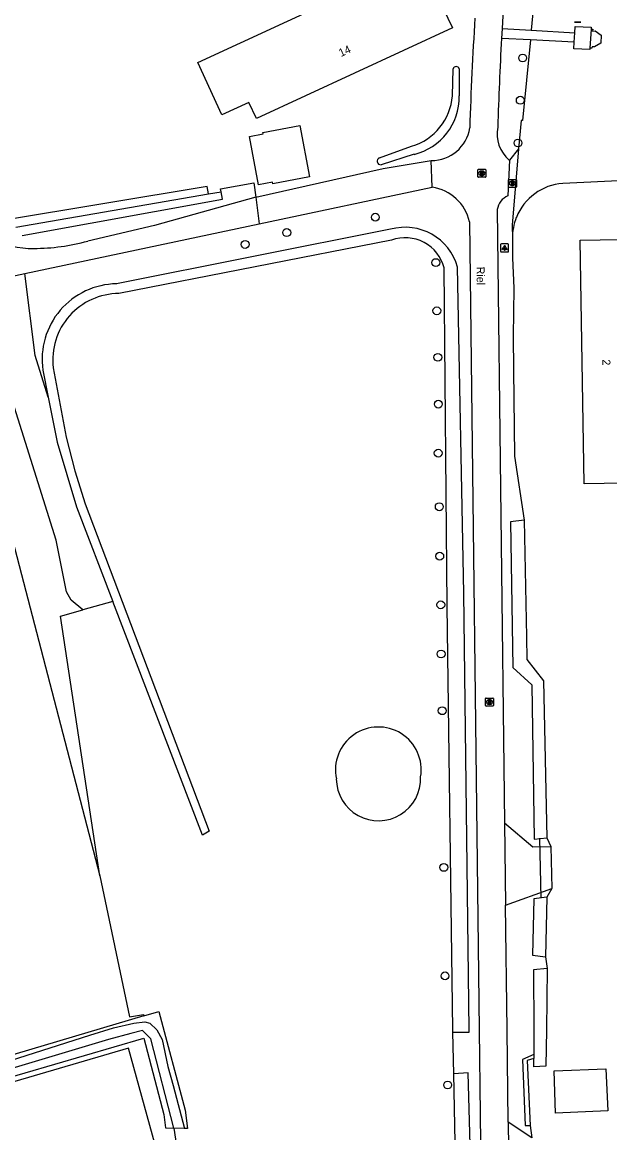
# Model space of a CAD drawing. Extents: x 163863 to 164644, y 379566 to 382155.
# Drawn here: x 164384.5 to 164457.9, y 381487.2 to 381625.9 of the extents above; entities that cross this region are included whole.
import ezdxf

# ---------------------------------------------------------------- set-up
doc = ezdxf.new("R2010")
doc.units = 0
for name, color, linetype in [('IMGEO_Boom', 7, 'Continuous'), ('IMGEO_Brandkraan', 7, 'Continuous'), ('IMGEO_Duiker', 7, 'Continuous'), ('IMGEO_Erf', 7, 'Continuous'), ('IMGEO_Grasland_overig', 7, 'Continuous'), ('IMGEO_Greppel_droge_sloot', 7, 'Continuous'), ('IMGEO_Groenvoorziening', 7, 'Continuous'), ('IMGEO_Haag', 7, 'Continuous'), ('IMGEO_Informatiebord', 7, 'Continuous'), ('IMGEO_Lichtpunt', 7, 'Continuous'), ('IMGEO_Loofbos', 7, 'Continuous'), ('IMGEO_Openbare_ruimte_label', 7, 'Continuous'), ('IMGEO_Pand', 7, 'Continuous'), ('IMGEO_Pand_nummerreeks', 7, 'Continuous'), ('IMGEO_Rijbaan_lokaal_gesloten', 7, 'Continuous'), ('IMGEO_Rijbaan_lokaal_halfverhard', 7, 'Continuous'), ('IMGEO_Rijbaan_lokaal_onverhard', 7, 'Continuous'), ('IMGEO_Rioolput', 7, 'Continuous'), ('IMGEO_Voetpad_open', 7, 'Continuous'), ('IMGEO_Waterloop', 7, 'Continuous')]:
    doc.layers.add(name, color=color, linetype=linetype)

msp = doc.modelspace()

# ---------------------------------------------------------------- linework, layer by layer
at = {"layer": 'IMGEO_Boom'}
for centre in [(164447.05, 381621.41), (164446.75, 381616.13), (164446.46, 381610.79), (164428.64, 381601.52), (164417.58, 381599.6), (164412.38, 381598.12), (164436.2, 381595.85), (164436.33, 381589.83), (164436.46, 381584.02), (164436.51, 381578.17), (164436.5, 381572.05), (164436.63, 381565.35), (164436.69, 381559.18), (164436.82, 381553.1), (164436.86, 381546.96), (164437, 381539.87), (164437.2, 381520.3), (164437.35, 381506.75), (164437.68, 381493.12)]:
    msp.add_circle(centre, 0.489, dxfattribs=at)
at = {"layer": 'IMGEO_Brandkraan'}
for p, q in [((164445.26, 381605.33), (164445.26, 381606.18)), ((164445.34, 381606.25), (164446.19, 381606.25)), ((164446.26, 381606.18), (164446.26, 381605.33)), ((164446.19, 381605.25), (164445.34, 381605.25)), ((164445.75, 381606.03), (164445.77, 381606.03)), ((164445.77, 381605.47), (164445.75, 381605.47))]:
    msp.add_line(p, q, dxfattribs=at)
for points in [[(164445.26, 381605.33), (164445.26, 381606.18)], [(164445.34, 381606.25), (164446.19, 381606.25)], [(164446.26, 381606.18), (164446.26, 381605.33)], [(164446.19, 381605.25), (164445.34, 381605.25)], [(164445.61, 381605.95), (164445.61, 381605.55), (164445.82, 381605.55)], [(164445.84, 381605.95), (164445.61, 381605.95)], [(164445.79, 381605.87), (164445.73, 381605.87), (164445.73, 381605.8)], [(164445.73, 381605.8), (164445.79, 381605.8)], [(164445.8, 381605.72), (164445.73, 381605.72), (164445.73, 381605.64)], [(164445.73, 381605.64), (164445.8, 381605.64)]]:
    msp.add_lwpolyline(points, dxfattribs=at)
for centre, radius, start, end in [((164445.34, 381606.18), 0.0765, 91.552, 178.448), ((164445.34, 381606.18), 0.0765, 91.552, 178.448), ((164446.19, 381606.18), 0.0765, 1.552, 88.448), ((164446.19, 381606.18), 0.0765, 1.552, 88.448), ((164445.34, 381605.33), 0.0765, 181.552, 268.448), ((164445.34, 381605.33), 0.0765, 181.552, 268.448), ((164445.79, 381605.83), 0.0379, 267.8285, 90.9355), ((164445.8, 381605.68), 0.0404, 269.8759, 90.5077), ((164445.83, 381605.8), 0.251, 268.6676, 293.5347), ((164445.84, 381605.81), 0.145, 59.4692, 91.5367), ((164445.87, 381605.86), 0.0922, 285.5137, 58.1501), ((164445.87, 381605.66), 0.105, 301.3115, 78.989), ((164446.19, 381605.33), 0.0765, 271.552, 358.448), ((164446.19, 381605.33), 0.0765, 271.552, 358.448)]:
    msp.add_arc(centre, radius, start, end, dxfattribs=at)
for centre, major_axis, ratio, start_param, end_param in [((164445.75, 381605.75), (-0.387, 0.002), 0.722429, 4.712389, 7.853982), ((164445.77, 381605.75), (-0.39, 0.002), 0.717154, 1.570796, 4.712389)]:
    msp.add_ellipse(centre, major_axis=major_axis, ratio=ratio, start_param=start_param, end_param=end_param, dxfattribs=at)
at = {"layer": 'IMGEO_Duiker'}
msp.add_lwpolyline([(164449.15, 381523.97), (164449.33, 381516.45)], dxfattribs=at)
at = {"layer": 'IMGEO_Erf'}
msp.add_lwpolyline([(164399.71, 381501.75), (164380.24, 381495.98)], dxfattribs=at)
at = {"layer": 'IMGEO_Grasland_overig'}
for points in [[(164392.11, 381552.47), (164390.65, 381553.68), (164390.08, 381554.71), (164388.77, 381561.19), (164381.76, 381583.47), (164380.51, 381593.56)], [(164375.48, 381589.55), (164377.05, 381585.25), (164394.23, 381519.23)], [(164348.35, 381518.62), (164349.7, 381517.97), (164353.09, 381515.54), (164355.98, 381512.51), (164367, 381500.41), (164372.5, 381495.24), (164374.19, 381493.46), (164376.45, 381492.51), (164378.9, 381492.55), (164381.15, 381493.56), (164399.72, 381498.97), (164402.22, 381489.44), (164402.44, 381487.77), (164403.46, 381487.71)], [(164404.26, 381474.32), (164397.81, 381497.74), (164374.92, 381491), (164348.35, 381518.62)], [(164448.45, 381496.92), (164447.04, 381496.29), (164447.36, 381488.05), (164447.99, 381488.08)], [(164448.45, 381496.45), (164447.62, 381496.18), (164447.99, 381488.08)]]:
    msp.add_lwpolyline(points, dxfattribs=at)
at = {"layer": 'IMGEO_Greppel_droge_sloot'}
for points in [[(164438.27, 381616.7), (164438.38, 381620.04)], [(164439.11, 381620.04), (164439.12, 381616.67)], [(164429.16, 381608.94), (164433.18, 381610.4)], [(164433.49, 381609.38), (164429.36, 381608.07)]]:
    msp.add_lwpolyline(points, dxfattribs=at)
for centre, radius, start, end in [((164438.74, 381619.97), 0.374, 10.7468, 169.8768), ((164431.19, 381617.21), 7.1, 286.3074, 355.8959), ((164431.74, 381616.55), 7.39, 283.7517, 0.901), ((164429.33, 381608.52), 0.455, 112.0307, 273.6908)]:
    msp.add_arc(centre, radius, start, end, dxfattribs=at)
at = {"layer": 'IMGEO_Groenvoorziening'}
for points in [[(164452.88, 381674.52), (164448.12, 381624.87)], [(164446.54, 381610.04), (164445.73, 381600.53), (164445.79, 381598.85)], [(164473.79, 381606.76), (164452.07, 381605.75)], [(164409.37, 381604.7), (164409.29, 381605.07), (164413.47, 381605.82), (164413.71, 381604.01)], [(164445.79, 381598.85), (164445.76, 381596.44), (164445.96, 381592.66), (164445.85, 381586.66), (164445.92, 381582.44), (164446.04, 381571.66), (164447.24, 381563.68)], [(164387.77, 381579.05), (164386.14, 381584.23), (164384.86, 381594.48)], [(164450.08, 381523.98), (164450.55, 381522.92)], [(164450.68, 381517.67), (164450.07, 381516.57)], [(164449.91, 381509.12), (164450.1, 381507.69)], [(164447.99, 381488.08), (164448.2, 381486.51)]]:
    msp.add_lwpolyline(points, dxfattribs=at)
for centre, radius, start, end in [((164452.55, 381599), 6.76, 94.0969, 158.32), ((164452.52, 381599), 6.74, 158.2733, 181.2961)]:
    msp.add_arc(centre, radius, start, end, dxfattribs=at)
at = {"layer": 'IMGEO_Haag'}
msp.add_lwpolyline([(164407.8, 381604.43), (164407.63, 381605.35), (164382.05, 381601.1), (164338.92, 381665.18), (164338.35, 381664.78)], dxfattribs=at)
at = {"layer": 'IMGEO_Informatiebord'}
for p, q in [((164454.33, 381625.88), (164453.54, 381625.88)), ((164453.54, 381625.88), (164454.33, 381625.88))]:
    msp.add_line(p, q, dxfattribs=at)
at = {"layer": 'IMGEO_Lichtpunt'}
for p, q in [((164444.3, 381598.09), (164444.3, 381597.28)), ((164444.3, 381598.09), (164444.3, 381597.28)), ((164445.2, 381598.18), (164444.39, 381598.18)), ((164445.2, 381598.18), (164444.39, 381598.18)), ((164445.29, 381597.28), (164445.29, 381598.09)), ((164445.29, 381597.28), (164445.29, 381598.09)), ((164444.39, 381597.18), (164445.2, 381597.18)), ((164444.39, 381597.18), (164445.2, 381597.18))]:
    msp.add_line(p, q, dxfattribs=at)
for points in [[(164444.67, 381597.75), (164444.71, 381597.72), (164444.52, 381597.46), (164444.48, 381597.49), (164444.67, 381597.75)], [(164444.88, 381597.72), (164444.92, 381597.75), (164445.11, 381597.49), (164445.07, 381597.46), (164444.88, 381597.72)], [(164444.77, 381597.7), (164444.82, 381597.7), (164444.82, 381597.38), (164444.77, 381597.38), (164444.77, 381597.7)]]:
    msp.add_lwpolyline(points, dxfattribs=at)
msp.add_circle((164444.8, 381597.88), 0.0994, dxfattribs=at)
for centre, start, end in [((164444.39, 381598.09), 90, 180), ((164444.39, 381598.09), 90, 180), ((164445.2, 381598.09), 0, 90), ((164445.2, 381598.09), 0, 90), ((164444.39, 381597.28), 180, 270), ((164444.39, 381597.28), 180, 270), ((164445.2, 381597.28), 270, 0), ((164445.2, 381597.28), 270, 360)]:
    msp.add_arc(centre, 0.0946, start, end, dxfattribs=at)
at = {"layer": 'IMGEO_Loofbos'}
for points in [[(164448.01, 381623.67), (164447.04, 381613.6), (164446.85, 381613.61), (164446.54, 381610.04)], [(164446.54, 381610.04), (164445.39, 381608.65)], [(164395.86, 381553.52), (164392.11, 381552.47)], [(164394.23, 381519.23), (164389.32, 381551.69), (164392.11, 381552.47)], [(164394.23, 381519.23), (164397.93, 381501.62), (164399.68, 381501.92), (164399.71, 381501.75)], [(164399.71, 381501.75), (164401.6, 381502.3), (164404.9, 381489.96), (164405.2, 381487.7), (164404.81, 381487.67)], [(164438.46, 381494.53), (164438.34, 381499.7)], [(164403.46, 381487.71), (164404.03, 381484.15)]]:
    msp.add_lwpolyline(points, dxfattribs=at)
for centre, radius, start, end in [((164429.02, 381532.48), 5.36, 350.5628, 192.1236), ((164429.04, 381531.4), 5.27, 180.5064, 2.18)]:
    msp.add_arc(centre, radius, start, end, dxfattribs=at)
at = {"layer": 'IMGEO_Pand'}
for points in [[(164434.22, 381633.69), (164438.27, 381625.17), (164413.78, 381613.84), (164412.85, 381615.86), (164409.48, 381614.3), (164406.45, 381620.84), (164434.22, 381633.69)], [(164455.59, 381625), (164455.46, 381622.64)], [(164455.59, 381625), (164455.8, 381624.99), (164455.79, 381624.77), (164456.11, 381624.78), (164456.86, 381624.28), (164456.82, 381623.27), (164456.04, 381622.8), (164455.72, 381622.82), (164455.71, 381622.62), (164455.46, 381622.64)], [(164412.91, 381611.62), (164414.64, 381611.95), (164414.61, 381612.12), (164419.21, 381612.99), (164420.42, 381606.58), (164415.82, 381605.7), (164415.78, 381605.88), (164414.06, 381605.55), (164412.91, 381611.62)], [(164464.35, 381568.37), (164459.74, 381568.3), (164454.74, 381568.22), (164454.24, 381598.65), (164459.24, 381598.75), (164463.87, 381598.84), (164464.35, 381568.37)], [(164457.68, 381489.91), (164451.15, 381489.61), (164450.97, 381494.89), (164457.45, 381495.15), (164457.68, 381489.91)]]:
    msp.add_lwpolyline(points, dxfattribs=at)
at = {"layer": 'IMGEO_Rijbaan_lokaal_gesloten'}
for points in [[(164444.47, 381625.08), (164444.44, 381624.46), (164444.4, 381623.85)], [(164435.74, 381605.27), (164435.64, 381608.59)], [(164445.39, 381608.65), (164445.21, 381604.21)], [(164443.88, 381602.47), (164444.8, 381525.85)], [(164440.42, 381600.95), (164441.6, 381500), (164441.98, 381468.27), (164442.05, 381465.53), (164442.22, 381458.62), (164442.22, 381457.68)], [(164444.8, 381525.85), (164444.92, 381515.57)], [(164445.25, 381488.48), (164445.11, 381500), (164444.92, 381515.57)], [(164445.25, 381488.48), (164445.36, 381478.81)]]:
    msp.add_lwpolyline(points, dxfattribs=at)
for centre, radius, start, end in [((164886.52, 381599.85), 442.77, 170.1772, 176.7344), ((164930.76, 381596.32), 490.6, 176.4854, 178.0894), ((164883.32, 381600.01), 439.56, 176.8905, 178.3368), ((164435.65, 381613.44), 4.85, 269.9071, 350.8532), ((164448.06, 381611.91), 4.21, 168.2264, 230.5312), ((164434.91, 381599.68), 5.65, 12.9621, 81.5794), ((164446.13, 381602.13), 2.27, 113.8211, 171.5393)]:
    msp.add_arc(centre, radius, start, end, dxfattribs=at)
at = {"layer": 'IMGEO_Rijbaan_lokaal_halfverhard'}
for points in [[(164413.71, 381604.01), (164429.61, 381607.59), (164435.64, 381608.59)], [(164414.14, 381600.68), (164435.74, 381605.27)], [(164413.71, 381604.01), (164414.14, 381600.68)]]:
    msp.add_lwpolyline(points, dxfattribs=at)
at = {"layer": 'IMGEO_Rijbaan_lokaal_onverhard'}
for points in [[(164413.71, 381604.01), (164401.06, 381600.47), (164392.72, 381598.54)], [(164384.86, 381594.48), (164414.14, 381600.68)], [(164380.51, 381593.56), (164384.86, 381594.48)]]:
    msp.add_lwpolyline(points, dxfattribs=at)
for centre, radius, start, end in [((164385.9, 381609.07), 11.46, 242.7973, 270.3915), ((164385.95, 381623.04), 25.42, 270.0677, 285.4619)]:
    msp.add_arc(centre, radius, start, end, dxfattribs=at)
at = {"layer": 'IMGEO_Rioolput'}
for p, q in [((164441.45, 381606.58), (164441.45, 381607.43)), ((164441.52, 381607.51), (164442.38, 381607.51)), ((164442.45, 381607.43), (164442.45, 381606.58)), ((164442.38, 381606.51), (164441.52, 381606.51)), ((164441.94, 381607.29), (164441.96, 381607.29)), ((164441.96, 381606.73), (164441.94, 381606.73)), ((164442.41, 381540.52), (164442.41, 381541.38)), ((164442.48, 381541.45), (164443.33, 381541.45)), ((164442.89, 381541.23), (164442.92, 381541.23)), ((164443.41, 381541.38), (164443.41, 381540.52)), ((164443.33, 381540.45), (164442.48, 381540.45)), ((164442.92, 381540.67), (164442.89, 381540.67))]:
    msp.add_line(p, q, dxfattribs=at)
for points in [[(164441.45, 381606.58), (164441.45, 381607.43)], [(164441.52, 381607.51), (164442.38, 381607.51)], [(164442.45, 381607.43), (164442.45, 381606.58)], [(164442.38, 381606.51), (164441.52, 381606.51)], [(164442.04, 381607.2), (164441.79, 381607.21), (164441.79, 381606.81)], [(164441.79, 381606.81), (164441.91, 381606.81), (164441.91, 381606.97), (164441.92, 381606.97)], [(164441.97, 381607.13), (164441.91, 381607.13), (164441.91, 381607.04)], [(164441.91, 381607.04), (164441.96, 381607.04)], [(164441.97, 381606.94), (164442.04, 381606.81), (164442.18, 381606.81), (164442.11, 381606.93)], [(164442.41, 381540.52), (164442.41, 381541.38)], [(164442.48, 381541.45), (164443.33, 381541.45)], [(164442.99, 381541.15), (164442.74, 381541.15), (164442.74, 381540.75)], [(164442.74, 381540.75), (164442.87, 381540.75), (164442.87, 381540.91), (164442.88, 381540.91)], [(164442.92, 381541.07), (164442.87, 381541.07), (164442.87, 381540.99)], [(164442.87, 381540.99), (164442.92, 381540.99)], [(164442.92, 381540.88), (164443, 381540.75), (164443.13, 381540.75), (164443.07, 381540.88)], [(164443.41, 381541.38), (164443.41, 381540.52)], [(164443.33, 381540.45), (164442.48, 381540.45)]]:
    msp.add_lwpolyline(points, dxfattribs=at)
for centre, radius, start, end in [((164441.53, 381607.43), 0.0765, 91.552, 178.448), ((164441.53, 381607.43), 0.0765, 91.552, 178.448), ((164442.37, 381607.43), 0.0765, 1.552, 88.448), ((164442.37, 381607.43), 0.0765, 1.552, 88.448), ((164441.53, 381606.58), 0.0765, 181.552, 268.448), ((164441.53, 381606.58), 0.0765, 181.552, 268.448), ((164441.92, 381606.92), 0.0533, 26.0293, 88.6989), ((164441.95, 381607.23), 0.19, 274.7715, 282.9687), ((164441.97, 381607.03), 0.0964, 77.0061, 93.1865), ((164441.99, 381607.09), 0.0378, 276.6634, 79.6772), ((164442.04, 381607.09), 0.109, 350.3612, 89.416), ((164442.04, 381607.09), 0.112, 277.5842, 350.9817), ((164442.02, 381606.88), 0.108, 29.5134, 73.7905), ((164442.37, 381606.58), 0.0765, 271.552, 358.448), ((164442.37, 381606.58), 0.0765, 271.552, 358.448), ((164442.48, 381541.37), 0.0765, 91.552, 178.448), ((164442.48, 381541.37), 0.0765, 91.552, 178.448), ((164442.88, 381540.86), 0.0533, 26.0293, 88.6989), ((164442.93, 381540.97), 0.0964, 77.0061, 93.1865), ((164442.9, 381541.18), 0.19, 274.7715, 282.9687), ((164442.94, 381541.03), 0.0378, 276.6634, 79.6772), ((164442.99, 381541.04), 0.109, 350.3612, 89.416), ((164442.99, 381541.04), 0.112, 277.5842, 350.9817), ((164442.98, 381540.82), 0.108, 29.5134, 73.7905), ((164443.33, 381541.37), 0.0765, 1.552, 88.448), ((164443.33, 381541.37), 0.0765, 1.552, 88.448), ((164442.48, 381540.52), 0.0765, 181.552, 268.448), ((164442.48, 381540.52), 0.0765, 181.552, 268.448), ((164443.33, 381540.52), 0.0765, 271.552, 358.448), ((164443.33, 381540.52), 0.0765, 271.552, 358.448)]:
    msp.add_arc(centre, radius, start, end, dxfattribs=at)
for centre, major_axis, ratio, start_param, end_param in [((164441.94, 381607.01), (-0.387, 0.002), 0.722429, 4.712389, 7.853982), ((164441.96, 381607.01), (-0.39, 0.002), 0.717154, 1.570796, 4.712389), ((164442.89, 381540.95), (-0.387, 0.002), 0.722429, 4.712389, 7.853982), ((164442.92, 381540.95), (-0.39, 0.002), 0.717154, 1.570796, 4.712389)]:
    msp.add_ellipse(centre, major_axis=major_axis, ratio=ratio, start_param=start_param, end_param=end_param, dxfattribs=at)
at = {"layer": 'IMGEO_Voetpad_open'}
for points in [[(164444.47, 381625.08), (164448.12, 381624.87)], [(164448.12, 381624.87), (164453.56, 381624.57)], [(164453.5, 381623.38), (164453.56, 381624.57)], [(164453.56, 381624.57), (164453.61, 381625.36), (164455.59, 381625.27), (164455.59, 381625)], [(164448.01, 381623.67), (164444.4, 381623.85)], [(164453.5, 381623.38), (164448.01, 381623.67)], [(164455.46, 381622.64), (164455.45, 381622.46), (164453.45, 381622.56), (164453.5, 381623.38)], [(164444.8, 381525.85), (164448.32, 381522.87), (164450.55, 381522.92)], [(164450.55, 381522.92), (164450.68, 381517.67)], [(164444.92, 381515.57), (164450.68, 381517.67)], [(164448.2, 381486.51), (164445.25, 381488.48)]]:
    msp.add_lwpolyline(points, dxfattribs=at)
at = {"layer": 'IMGEO_Waterloop'}
for points in [[(164384.53, 381599.22), (164409.57, 381603.76), (164409.37, 381604.7)], [(164407.8, 381604.43), (164409.37, 381604.7)], [(164383.73, 381600.26), (164407.8, 381604.43)], [(164430.54, 381600.01), (164396.33, 381593.2)], [(164430.68, 381598.65), (164396.62, 381591.99)], [(164438.34, 381499.7), (164438.34, 381500), (164437.6, 381552.99), (164437.24, 381595.18)], [(164438.34, 381499.7), (164440.38, 381499.71), (164440.38, 381500), (164439.69, 381554.54), (164438.92, 381595.29)], [(164388.41, 381582.72), (164390.02, 381574.06), (164391.09, 381569.85), (164392.41, 381565.7), (164407.87, 381524.82), (164407.05, 381524.34), (164395.86, 381553.52)], [(164387.11, 381582.42), (164387.77, 381579.05)], [(164387.77, 381579.05), (164388.89, 381573.41), (164391.32, 381565.35), (164395.86, 381553.52)], [(164447.24, 381563.68), (164445.54, 381563.46), (164445.82, 381545.26), (164448.18, 381543.12), (164448.5, 381523.83), (164450.08, 381523.98)], [(164447.24, 381563.68), (164447.52, 381549.09), (164447.58, 381546.29), (164449.66, 381543.61), (164450.08, 381523.98)], [(164450.07, 381516.57), (164448.43, 381516.36), (164448.27, 381509.34), (164449.91, 381509.12)], [(164450.07, 381516.57), (164449.91, 381509.12)], [(164450.1, 381507.69), (164448.42, 381507.52), (164448.44, 381500), (164448.45, 381496.92)], [(164450.1, 381507.69), (164450.01, 381500), (164449.96, 381495.46), (164448.45, 381495.4), (164448.45, 381496.45)], [(164381.07, 381495.55), (164392.99, 381499.33), (164395.92, 381500.28), (164398.49, 381500.86), (164399.86, 381500.99), (164400.48, 381500.83), (164401.35, 381500), (164402, 381498.79), (164402.74, 381495.45), (164403.41, 381493.05), (164404.81, 381487.67)], [(164403.46, 381487.71), (164400.58, 381498.87), (164399.54, 381499.92), (164398.09, 381499.57), (164395.31, 381498.82), (164382.41, 381494.93)], [(164448.45, 381496.92), (164448.45, 381496.45)], [(164414.31, 381440.63), (164416.58, 381441.28), (164418.61, 381441.32), (164434.38, 381437.96), (164436.81, 381437.57), (164438.64, 381457.92), (164438.87, 381465.51), (164438.97, 381468.71), (164438.46, 381494.53)], [(164436.48, 381433.86), (164438.14, 381433.63), (164439.18, 381444.59), (164440.98, 381463.45), (164440.95, 381465.52), (164440.8, 381475.11), (164440.25, 381494.63), (164438.46, 381494.53)], [(164404.81, 381487.67), (164403.46, 381487.71)]]:
    msp.add_lwpolyline(points, dxfattribs=at)
for centre, radius, start, end in [((164432.36, 381593.44), 6.82, 15.7877, 105.4552), ((164432.39, 381593.94), 5.01, 14.3554, 109.9592), ((164396.45, 381583.77), 9.43, 90.7194, 188.1954), ((164396.63, 381583.71), 8.28, 90.0584, 186.8881)]:
    msp.add_arc(centre, radius, start, end, dxfattribs=at)

# ---------------------------------------------------------------- texts
at = {"layer": 'IMGEO_Openbare_ruimte_label'}
msp.add_text('Riel', height=1, rotation=270.5156, dxfattribs=at).set_placement((164441.3, 381595.34))
at = {"layer": 'IMGEO_Pand_nummerreeks'}
for s, rotation, p in [('14', 24.884, (164424.35, 381621.52)), ('2', 270.9487, (164457.01, 381583.75))]:
    msp.add_text(s, height=1, rotation=rotation, dxfattribs=at).set_placement(p)

doc.saveas('drawing.dxf')
